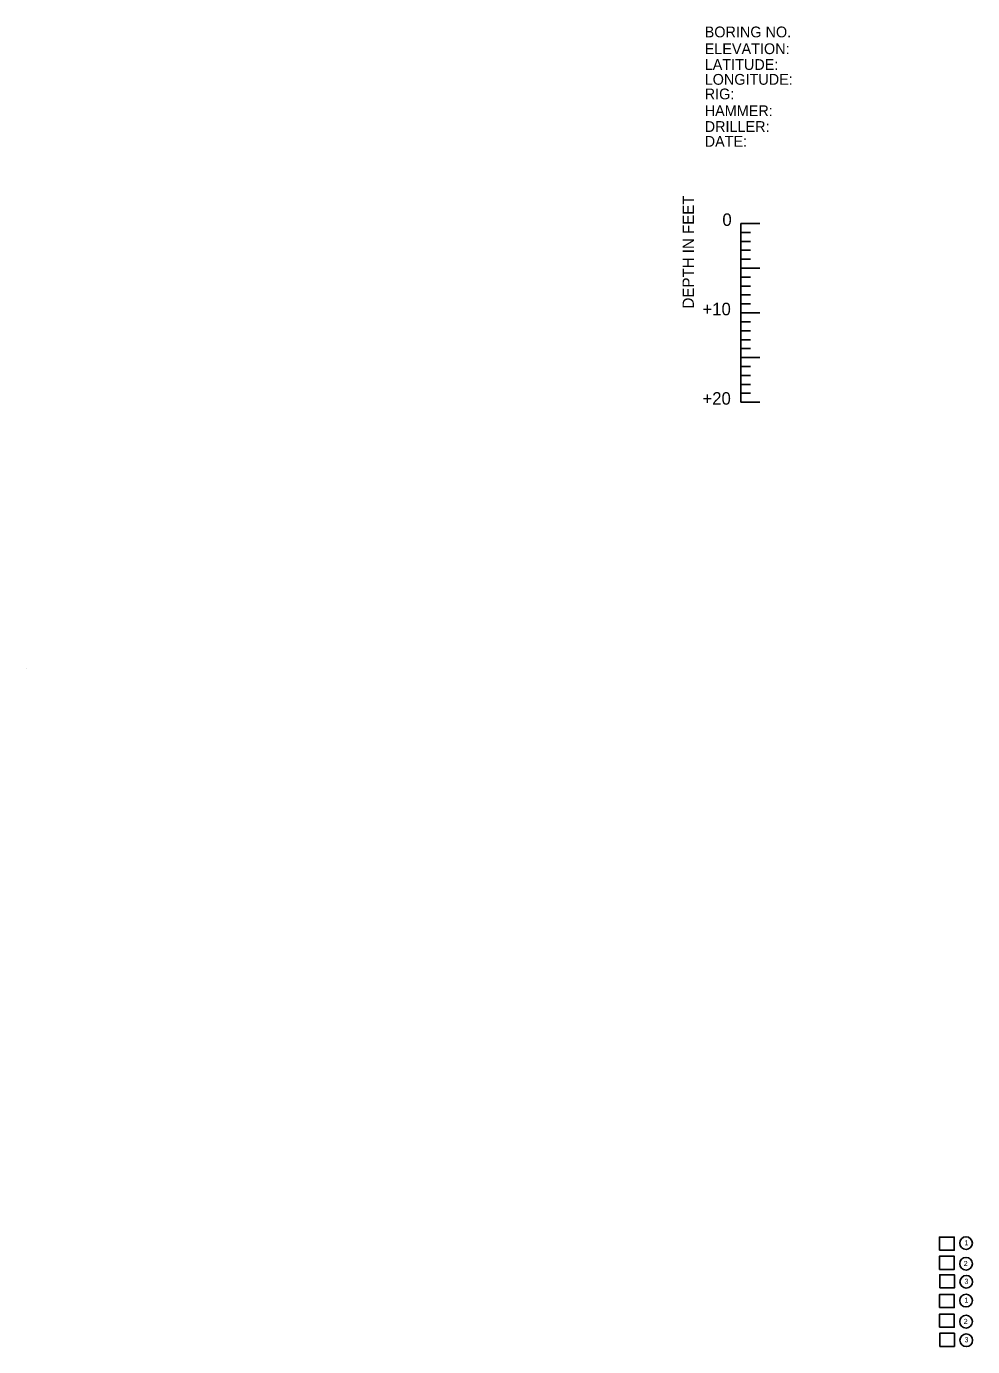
# Model space of a CAD drawing. Extents: x 0 to 331, y -72 to 117.
# Drawn here: x 0 to 28.35, y -20.31 to 19.26 of the extents above; entities that cross this region are included whole.
import ezdxf

# ---------------------------------------------------------------- set-up
doc = ezdxf.new("R2010")
doc.units = 0
for name, color, linetype in [('1-GRID', 7, 'Continuous'), ('1-TEXT', 7, 'Continuous'), ('Default', 7, 'Continuous')]:
    doc.layers.add(name, color=color, linetype=linetype)

msp = doc.modelspace()

# ---------------------------------------------------------------- linework, layer by layer
at = {"layer": '1-GRID'}
for p, q in [((21.411, 13.352), (21.976, 13.352)), ((21.411, 13.084), (21.697, 13.084)), ((21.411, 12.816), (21.697, 12.816)), ((21.411, 12.548), (21.697, 12.548)), ((21.411, 12.281), (21.697, 12.281)), ((21.411, 12.013), (21.976, 12.013)), ((21.411, 12.013), (21.976, 12.013)), ((21.411, 11.745), (21.697, 11.745)), ((21.411, 11.477), (21.697, 11.477)), ((21.411, 11.209), (21.697, 11.209)), ((21.411, 10.941), (21.697, 10.941)), ((21.411, 10.673), (21.976, 10.673)), ((21.411, 10.405), (21.697, 10.405)), ((21.411, 10.137), (21.697, 10.137)), ((21.411, 9.869), (21.697, 9.869)), ((21.411, 9.601), (21.697, 9.601)), ((21.411, 9.333), (21.976, 9.333)), ((21.411, 9.333), (21.976, 9.333)), ((21.411, 9.065), (21.697, 9.065)), ((21.411, 8.797), (21.697, 8.797)), ((21.411, 8.529), (21.697, 8.529)), ((21.411, 8.262), (21.697, 8.262)), ((21.411, 7.994), (21.976, 7.994))]:
    msp.add_line(p, q, dxfattribs=at)
for points in [[(21.411, 10.673), (21.411, 13.352)], [(21.411, 7.994), (21.411, 10.673)]]:
    msp.add_lwpolyline(points, dxfattribs=at)
at = {"layer": '1-TEXT'}
for points in [[(27.363, -17.42), (27.805, -17.42), (27.805, -17.027), (27.363, -17.027)], [(27.363, -17.994), (27.805, -17.994), (27.805, -17.601), (27.363, -17.601)], [(27.369, -18.55), (27.811, -18.55), (27.811, -18.157), (27.369, -18.157)], [(27.363, -19.141), (27.805, -19.141), (27.805, -18.748), (27.363, -18.748)], [(27.363, -19.73), (27.805, -19.73), (27.805, -19.337), (27.363, -19.337)], [(27.369, -20.302), (27.811, -20.302), (27.811, -19.909), (27.369, -19.909)]]:
    msp.add_lwpolyline(points, close=True, dxfattribs=at)
for centre in [(28.158, -17.208), (28.158, -17.825), (28.165, -18.367), (28.158, -18.929), (28.158, -19.561), (28.165, -20.118)]:
    msp.add_circle(centre, 0.19, dxfattribs=at)
at = {"layer": 'Default'}
msp.add_lwpolyline([(0, 0), (0, 0), (0, 0), (0, 0)], close=True, dxfattribs=at)

# ---------------------------------------------------------------- texts
at = {"layer": '1-GRID'}
msp.add_text('DEPTH IN FEET', height=0.3376, rotation=90, dxfattribs=at).set_placement((20.002, 10.804))
for s, height, p in [('0', 0.375, (20.857, 13.279)), ('+10', 0.3751, (20.259, 10.6)), ('+20', 0.3751, (20.259, 7.921))]:
    msp.add_text(s, height=height, dxfattribs=at).set_placement(p)
at = {"layer": '1-TEXT'}
for s, height, p in [('BORING NO.', 0.3231, (20.326, 18.93)), ('ELEVATION:', 0.3231, (20.326, 18.427)), ('LATITUDE:', 0.3231, (20.326, 17.953)), ('LONGITUDE:', 0.3231, (20.326, 17.509)), ('RIG:', 0.3231, (20.326, 17.072)), ('HAMMER:', 0.3231, (20.326, 16.569)), ('DRILLER:', 0.3231, (20.326, 16.095)), ('DATE:', 0.3231, (20.326, 15.651)), ('1', 0.152, (28.112, -17.271)), ('2', 0.152, (28.09, -17.893)), ('3', 0.152, (28.113, -18.426)), ('1', 0.152, (28.112, -18.991)), ('2', 0.152, (28.09, -19.629)), ('3', 0.152, (28.113, -20.178))]:
    msp.add_text(s, height=height, dxfattribs=at).set_placement(p)

doc.saveas('drawing.dxf')
